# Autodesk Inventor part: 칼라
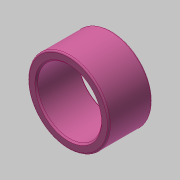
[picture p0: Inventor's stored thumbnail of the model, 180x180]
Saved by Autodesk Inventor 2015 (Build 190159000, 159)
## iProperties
Created: 2019-05
Part Number: 칼라
Material: 스테인리스강
Document SubType Name: Modeling
Designer: mduedu
Density: 1 g/cm^3
Appearance: 분홍색
Author: mduedu
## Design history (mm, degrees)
sketch "스케치1"
  geometry: C1 r 11 at (0, 0); C2 r 14 at (0, 0); 1 further point
  constraints: 2 centre point, 2 coincident
  dimensions: "d0" = 22 diameter of C1; "d1" = 28 diameter of C2
extrude "돌출1" new body sketch "스케치1" distance "d2" = 15; taper "d3" = 0 deg
fillet "모깎기1" dims "d4" = 0.5
chamfer "모따기1" distance "d5" = 0.5; stored, may be unused: second distance "d6" = 2, angle "d7" = 45 deg
node "솔리드1"
